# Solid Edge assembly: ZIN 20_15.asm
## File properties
Title: Zylinder
Author: bmolnar
Template: iso metric assembly.asm
Last saved by: bmolnar
Revision: 10
Application: Solid Edge
Username: bmolnar
Dokumentum tartalom típus: 1
Document Number: ZIN 20/15
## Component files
Kit_1.par
Kit_2.par
Profilrohr.par
Kolbenstange.par
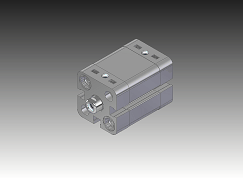
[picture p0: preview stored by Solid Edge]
